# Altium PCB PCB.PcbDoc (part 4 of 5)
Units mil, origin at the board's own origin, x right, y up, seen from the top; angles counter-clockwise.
Board outline 6700 x 6500 mil, 2 copper layers (Top Layer, Bottom Layer); 203 components, 278 nets, 1296 pads, 461 vias.
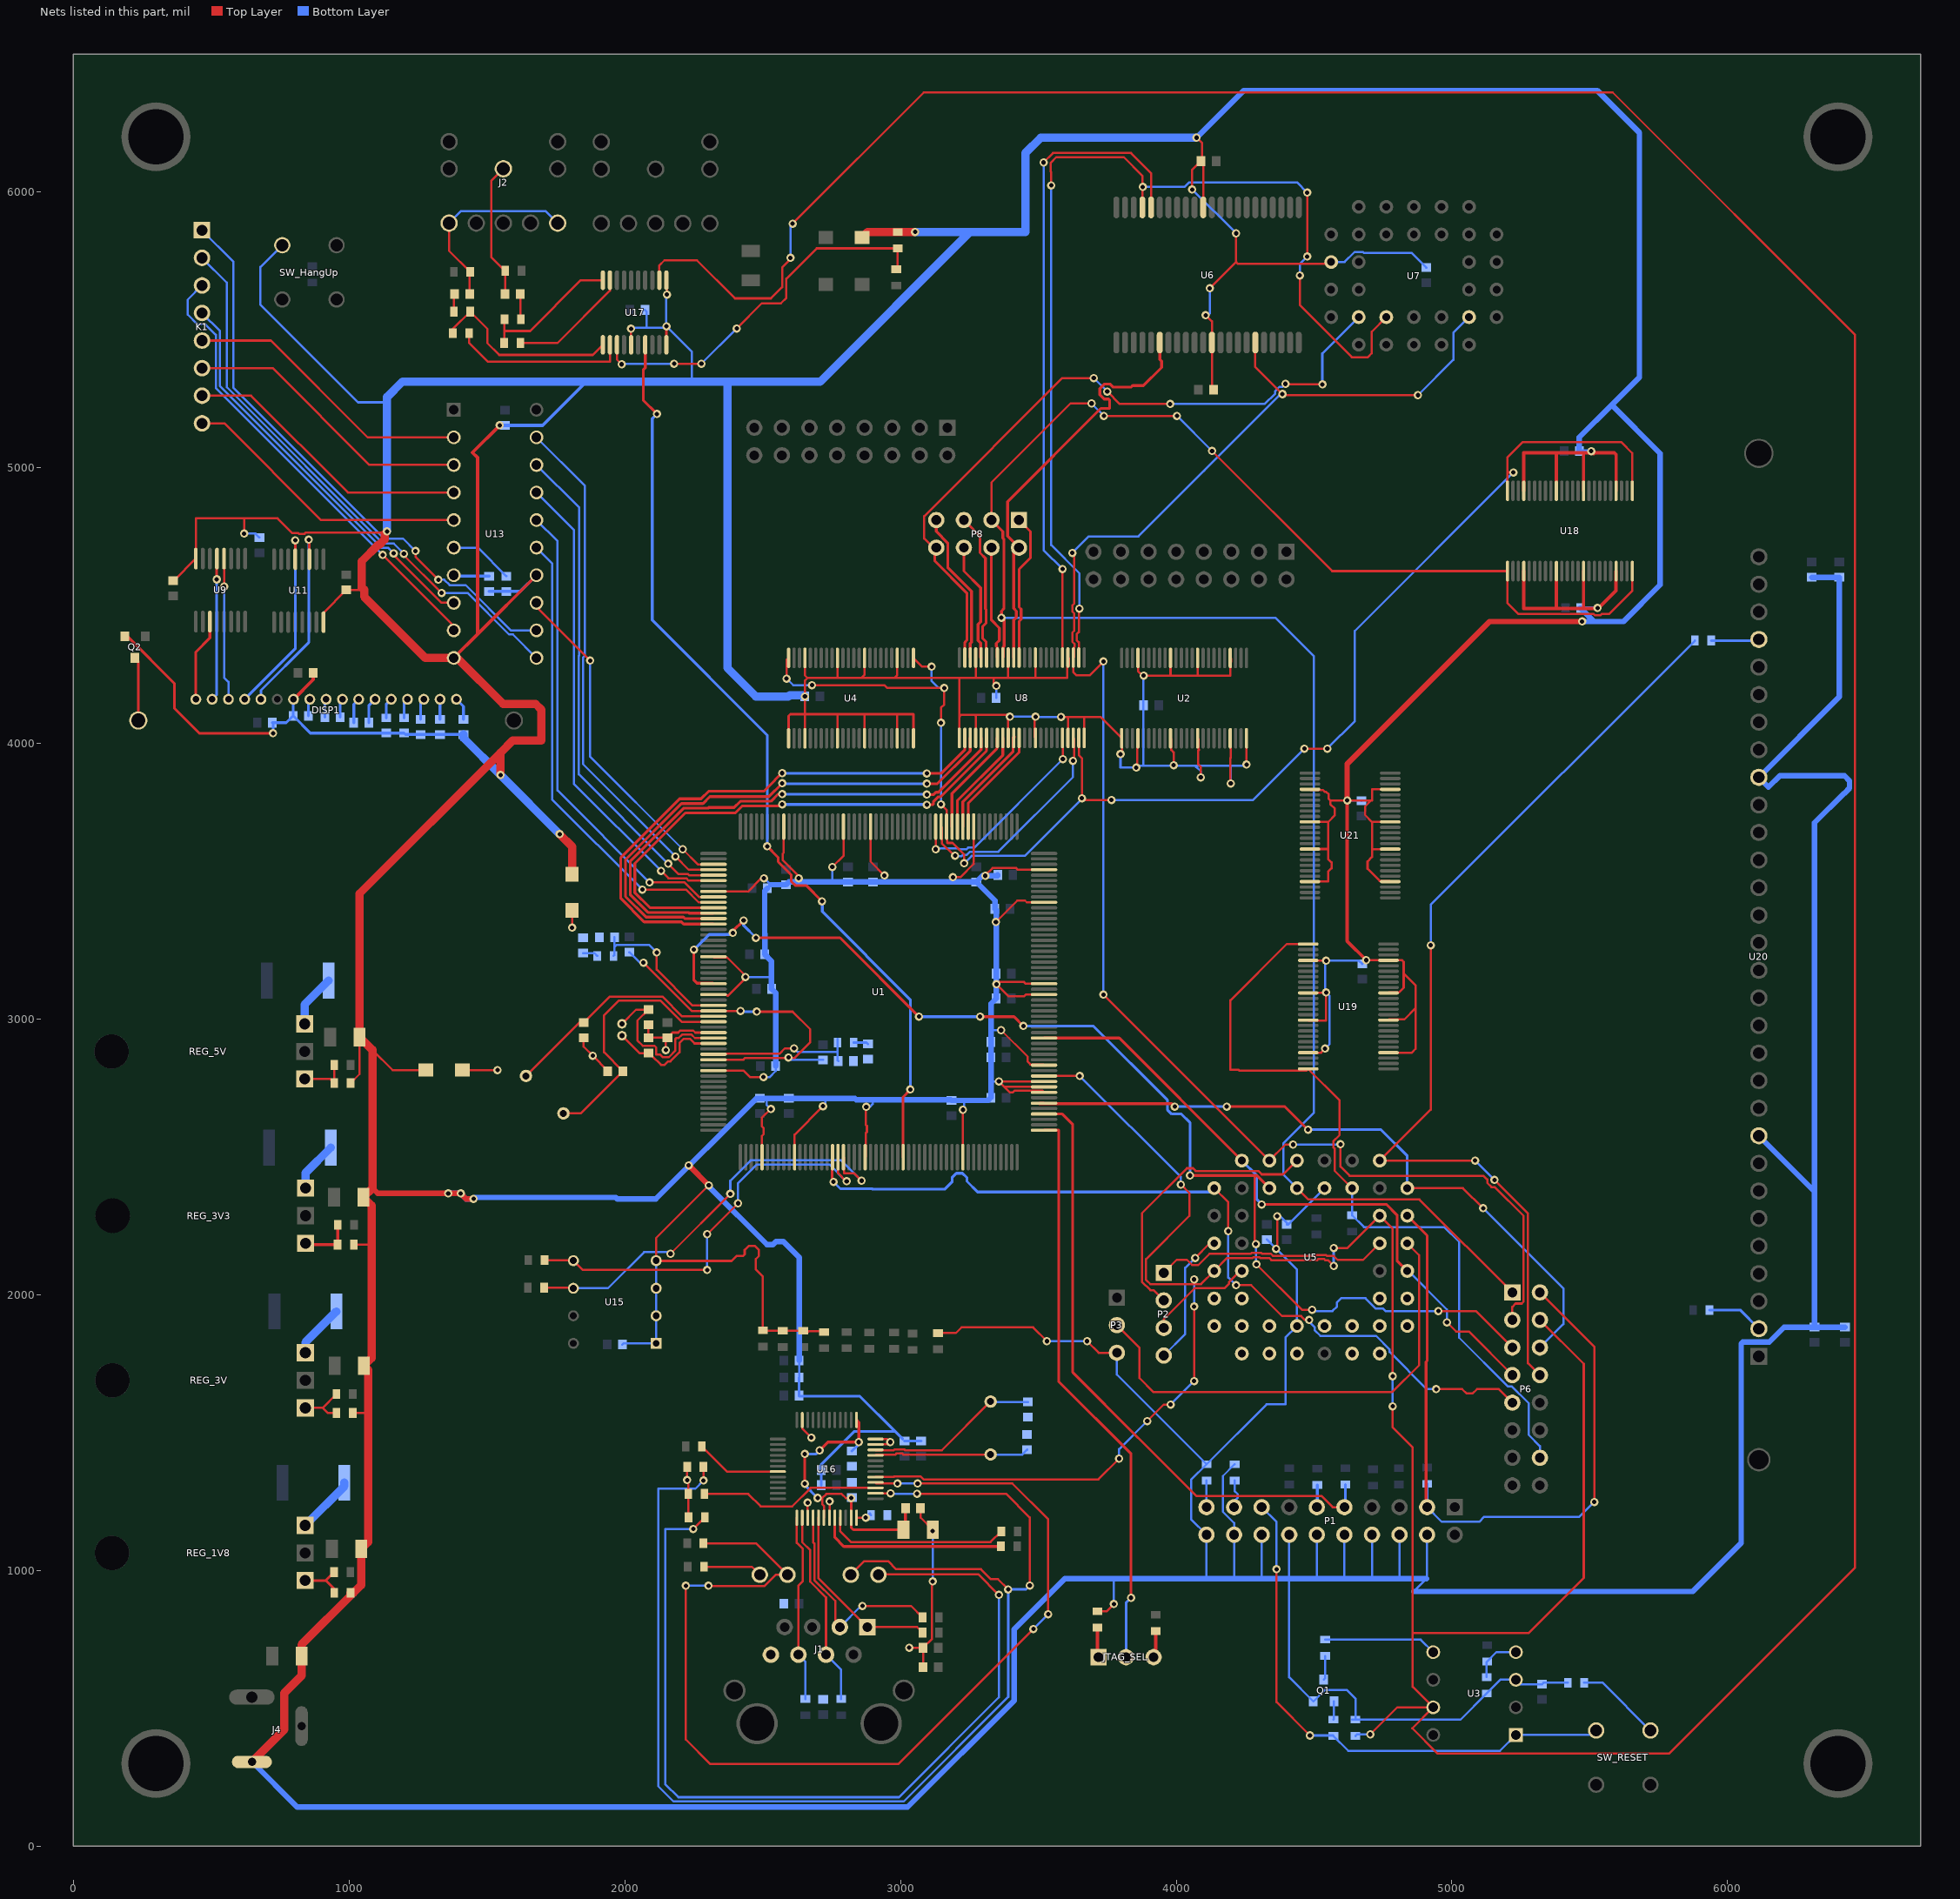
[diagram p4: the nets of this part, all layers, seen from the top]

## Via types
v1: diameter 30, hole 16, Top Layer to Bottom Layer, 461 vias

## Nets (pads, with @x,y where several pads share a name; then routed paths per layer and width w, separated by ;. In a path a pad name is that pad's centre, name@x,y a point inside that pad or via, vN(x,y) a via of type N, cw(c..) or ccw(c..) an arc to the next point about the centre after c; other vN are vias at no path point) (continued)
GND: C1.2 C2.2 C3.2 C4.2 C5.1 C6.2 C7.1 C8.2 C9.1 C10.2 C11.1 C12.2 C13.1 C14.2 C16.2 C18.2 C20.2 C21.2 C24.2 C25.2 C32.2 C33.2 C34.2 C36.2 C37.2 C38.2 C39.2 C41.2 C43.2 C44.1 C45.1 C46.1 C47.1 C48.1 C49.2 C50.2 C51.2 C52.2 C53.2 C54.2 C56.2 C57.2 C59.2 C60.2 C61.2 C63.2 C65.2 C66.2 C67.2 C68.2 C69.2 C70.2 C71.1 C72.1 C74.1 C75.2 C76.1 C77.2 C78.1 C79.1 C81.2 C82.2 C83.2 C84.2 C85.2 C86.2 C87.2 C88.2 C89.2 C90.2 C91.2 C92.2 C93.2 DISP1.11 J1.8 J4.GND L2.2 L3.2 L4.2 P1.4 P1.6 P1.8 P1.10 P1.12 P1.14 P1.16 P1.18 P1.20 P3.3 Q1.2 Q2.S R4.1 R6.2 R13.2 R14.2 R19.1 R20.1 R21.1 R35.2 R36.1 R37.1 R38.1 R39.2 R40.2 R48.1 R50.1 R52.1 R54.1 R64.1 R65.2 R66.2 SW_HangUp.2 U1.8 U1.20 U1.27 U1.41 U1.57 U1.63 U1.76 U1.94 U1.112 U1.113 U1.114 U1.117 U1.130 U1.132 U1.147 U1.153 U1.165 U1.184 U1.189 U1.200 U2.4 U2.10 U2.15 U2.21 U2.25 U2.28 U2.34 U2.39 U2.45 U2.48 U3.3 U4.4 U4.10 U4.15 U4.21 U4.25 U4.28 U4.34 U4.39 U4.45 U4.48 U5.1 U5.23 U6.12 U6.34 U7.16 U8.4 U8.10 U8.15 U8.21 U8.25 U8.28 U8.34 U8.39 U8.45 U8.48 U9.8 U11.8 U13.10 U13.14 U15.1 U15.2 U15.3 U15.4 U16.15 U16.19 U16.35 U16.36 U16.47 U17.1 U17.15 U17.20 U18.4 U18.10 U18.15 U18.21 U18.28 U18.34 U18.39 U18.45 U19.4 U19.10 U19.15 U19.21 U19.28 U19.34 U19.39 U19.45 U20.9 U20.22 U21.4 U21.10 U21.15 U21.21 U21.28 U21.34 U21.39 U21.45 | length 69308.9
  Top Layer w8: C10.2@362,4590.56 364.82,4590.56 U9.8@444.43,4670.17 444.43,4816 620,4816 ; v1(620,4761) 620,4816 ; U11.8@907.57,4439.83 907.57,4474.01 C16.2@990,4556.44 1053.44,4556.44 1046,4563.88 ; R50.1@1005.53,2768 1038.15,2800.62 C74.1@1038.15,2935 ; R54.1@1013.53,1572 1068,1572 1069,1573 ; R52.1@1017.53,2182 1078,2182 1082,2186 ; 1085,2888.15 1158.15,2815 L4.2@1279.06,2815 ; v1(1138,4769) 1129.43,4760.43 1124.87,4765 843.23,4765 838.66,4760.43 818.34,4760.43 815.97,4762.8 794.43,4762.8 741.23,4816 620,4816 ; U17.15@2023.18,5445.75 v1(2023.18,5504.18) ; U17.20@2151.13,5445.75 v1(2151.13,5512.87) ; U17.1@2151.13,5680 2153,5678.13 v1(2153,5628) ; R20.1@2226.47,1376 v1(2226.47,1328.53) 2230.47,1324.53 R19.1@2230.47,1278 2231.47,1277 R21.1@2231.47,1193 ; v1(2305,2397) 2114,2206 U15.4@2114,2124 2115,2123 2387.23,2123 2405.23,2141 2428.79,2141 2435,2147.21 2435,2162.77 2450.23,2178 2471.77,2178 2487,2162.77 2487,2141.23 2476,2130.23 2476,2091.77 2501,2066.77 R39.2@2501,1871.53 2503,1869.53 R38.1@2573,1869.53 R37.1@2647,1869.53 2651,1865.53 2665.29,1865.53 2667.76,1868 2720.53,1868 R36.1@2723,1865.53 ; U1.41@2321.77,2813.39 2430.84,2813.39 2454.23,2790 v1(2503,2790) ; U1.27@2321.77,3088.98 2368.32,3088.98 2373.21,3084.08 2438,3148.87 v1(2438,3153) 2438,3157.09 2371.1,3223.99 2324.55,3223.99 U1.20@2321.77,3226.77 ; U1.8@2321.77,3462.99 2447.29,3462.99 2495.3,3511 v1(2505,3511) ; U1.57@2497.95,2499.41 2497.95,2576.65 2504.27,2582.96 2504.27,2604.5 2497.95,2610.82 2497.95,2642.95 2529,2674 v1(2530,2674) ; U1.200@2576.69,3698.23 2576.69,3603.45 2572.63,3599.39 2572.63,3577.37 2631,3519 v1(2631,3511) ; U4.25@2594.41,4018.66 2594.41,4099.41 2601,4106 2653.47,4106 ; U1.63@2616.06,2499.41 2616.06,2581.06 v1(2719,2684) ; U16.47@2643.89,1546 2643.89,1515.11 v1(2677,1482) ; U4.28@2653.47,4018.66 2653.47,4106 ; U4.21@2653.47,4310 2653.47,4246.54 2663,4237 ; U16.15@2663.57,1191.67 v1(2663.57,1246.43) ; U16.19@2742.31,1191.67 2743,1192.35 v1(2743,1251) ; v1(2753,3552) 2793.23,3592.23 U1.189@2793.23,3698.23 ; U4.34@2771.58,4018.66 2771.58,4105.58 2772,4106 ; U4.15@2771.58,4310 2771.58,4238.58 2770,4237 ; U4.39@2870,4018.66 2870,4105 2871,4106 ; U4.10@2870,4310 2870,4249 2858,4237 ; U1.76@2871.97,2499.41 2874.75,2502.19 2874.75,2587.41 2878.28,2590.95 2878.28,2612.49 2874.75,2616.02 2874.75,2680.75 v1(2876,2682) ; U1.184@2891.65,3698.23 2891.65,3571.35 v1(2942,3521) ; U16.35@2909.64,1457.42 2954.42,1457.42 v1(2963,1466) 2951.9,1477.1 U16.36@2909.64,1477.1 ; U4.45@2988.11,4018.66 2988.11,4104.89 2987,4106 ; U4.4@2988.11,4310 2988.11,4248.11 2977,4237 ; v1(3032,720) C81.2@3082.44,720 ; U4.48@3047.17,4018.66 3047.17,4105.84 3047,4106 2987,4106 ; C63.2@3073.12,1226 3073.12,1192.03 C61.2@3117.15,1148 v1(3117.15,1142.85) ; C86.2@3082.44,650 C81.2@3082.44,720 ; v1(3117.15,960.85) 3114.75,958.45 3114.75,752.31 C81.2@3082.44,720 ; R35.2@3136,1861.53 3201,1861.53 3221.47,1882 3481,1882 v1(3531,1832) ; v1(3190,3515) 3217.77,3515 3265.67,3562.9 U1.165@3265.67,3698.23 ; U8.25@3213.78,4020 3213.78,4097 ; U1.94@3226.3,2499.41 v1(3226.3,2671.3) ; U8.28@3272.84,4020 3272.84,4100.06 3270,4102.89 ; U8.21@3272.84,4311.34 3272.84,4237.84 3272,4237 ; v1(3308,3520) 3308,3522 3334.05,3548.05 3419.72,3548.05 3426.04,3541.73 U1.153@3520.59,3541.73 ; v1(3346,3352) 3423.94,3429.94 3451.71,3429.94 3458.02,3423.62 U1.147@3520.59,3423.62 ; v1(3347.56,4208.56) 3338,4218.12 3338,4237 ; v1(3365,2960) 3461.36,2863.64 3461.36,2845.75 3471.27,2835.85 3517.81,2835.85 U1.117@3520.59,2833.07 ; U8.34@3390.95,4020 3390.95,4090.95 v1(3397,4097) 3391.11,4102.89 3270,4102.89 ; U8.15@3393.44,4313.83 U8.15@3390.95,4311.34 3390.95,4240.95 3387,4237 ; U8.39@3489.37,4020 3486.59,4022.78 3486.59,4093.59 v1(3490,4097) ; U8.10@3489.37,4311.34 3489.37,4237.37 3489,4237 ; U1.112@3520.59,2734.65 3514.27,2740.96 3414.19,2740.96 3407.88,2734.65 3396.39,2734.65 3376.7,2754.33 ; U1.113@3520.59,2754.33 3376.7,2754.33 ; U1.114@3520.59,2774.02 v1(3357.02,2774.02) 3376.7,2754.33 ; U1.130@3520.59,3088.98 3454.75,3088.98 3448.43,3082.66 3392.34,3082.66 v1(3348,3127) 3355.66,3134.66 3448.43,3134.66 3454.75,3128.35 U1.132@3520.59,3128.35 ; v1(3582,4096) 3607,4096 ; U8.45@3607.48,4020 3607.48,4095.52 3607,4096 ; U8.4@3607.48,4311.34 3610.26,4308.56 3610.26,4283 3605,4277.74 3605,4237 3489,4237 ; U8.48@3666.54,4020 3666.54,4095.47 3666,4096 ; v1(3677,1832) 3719,1790 P3.3@3785,1790 ; R6.2@3714,852 3747,852 v1(3774,879) ; v1(3798,3961) 3804.11,3967.11 3804.11,4016.76 U2.25@3802.21,4018.66 3724.87,4096 3666,4096 ; v1(3855,3912) 3858.48,3915.48 3858.48,4015.88 U2.28@3861.26,4018.66 ; U2.21@3861.26,4310 3861.26,4262.74 3880,4244 v1(3882,4246) 3978,4246 ; U2.34@3979.37,4018.66 3982.15,4015.88 3982.15,3976.31 3991,3967.46 v1(3991,3921) ; U2.15@3979.37,4310 3979.37,4247.37 3978,4246 ; v1(4058,6009) 4058,6080.56 C3.2@4089.44,6112 C3.2@4094.44,6107 ; v1(4074,6197) 4094.44,6176.56 C3.2@4094.44,6107 ; U2.39@4077.8,4018.66 4080.57,4015.88 4080.57,3980.16 4083.26,3977.48 4083.26,3977.11 4080,3973.85 4080,3924.15 4089,3915.15 v1(4089,3877) ; U2.10@4077.8,4310 4077.8,4246.21 4078,4246 ; U6.34@4098,5944.08 4098,6103.44 C3.2@4094.44,6107 ; v1(4107,5553) 4129.5,5530.5 U6.12@4129.5,5454 4129.5,5289.06 C24.2@4135.56,5283 ; v1(4122,5651) 4217,5746 ; U2.45@4195.91,4018.66 4198,4016.57 4198,3948.02 4197,3947.02 4197,3856 v1(4198,3855) ; U2.4@4195.91,4310 4198.68,4307.22 4198.68,4296 4196,4293.32 4196,4246 4078,4246 ; v1(4217,5850) 4217,5746 ; U2.48@4254.96,4018.66 4254.96,3923.96 4255.92,3923 v1(4255,3923) ; v1(4362.44,2167) 4366,2170.56 v1(4366,2285) ; U19.45@4478.66,2878.47 4525.47,2878.47 v1(4540,2893) ; U19.39@4478.66,2996.58 4480.24,2995 4544,2995 v1(4544,3097) 4542,3095 U19.34@4478.66,3095 ; U19.28@4478.66,3213.11 4479.77,3212 v1(4544,3212) ; U21.45@4485,3498.78 4550.78,3498.78 4550.78,3534.68 4563.17,3547.07 4563.17,3568.6 4550.78,3580.99 4550.78,3616 ; U21.39@4485,3616.89 4549.89,3616.89 4550.78,3616 ; U21.34@4485,3715.32 4551.32,3715.32 ; U21.28@4485,3833.43 4487.78,3830.65 4532.59,3830.65 4539.12,3824.11 4544.1,3824.11 4553,3815.21 4553,3799 4559,3793 ; U7.16@4562,5746 4556,5740 4223,5740 4217,5746 ; v1(4689,3214) U19.21@4769.11,3214 ; U19.4@4770,2878.47 4854.47,2878.47 4868,2892 4868,3039.77 ; U19.10@4770,2996.58 4772.78,2999.35 4827.58,2999.35 4868,3039.77 ; U19.15@4770,3095 4772.78,3097.78 4808.5,3097.78 4825,3114.28 4825,3166 ; U19.21@4770,3213.11 U19.21@4769.11,3214 ; U21.4@4776.34,3498.78 4773.56,3501.56 4737.84,3501.56 4694,3545.4 4694,3571.77 4710.43,3588.19 4710.43,3615.58 ; U21.10@4776.34,3616.89 4773.56,3619.67 4761,3619.67 4756.91,3615.58 4710.43,3615.58 ; U21.15@4776.34,3715.32 4710.54,3715.32 4710.43,3715.43 ; U21.21@4776.34,3833.43 4710.43,3833.43 4710.43,3793 4707.23,3793 ; 2653.47,4106 2772,4106 ; 2653.47,4106 v1(2653.47,4170.54) 2653,4171 2653,4227 2663,4237 ; 2663,4237 2770,4237 ; 2770,4237 2858,4237 ; 2772,4106 2871,4106 ; 2858,4237 2977,4237 ; 2871,4106 2987,4106 ; 2977,4237 3215,4237 ; 3213.78,4097 3213.78,4235.78 3215,4237 ; 3213.78,4097 3219.67,4102.89 3270,4102.89 ; 3215,4237 3272,4237 ; 3272,4237 3338,4237 ; 3338,4237 3387,4237 ; 3387,4237 3489,4237 ; 3607,4096 3666,4096 ; 3978,4246 4078,4246 ; 4550.78,3616 4550.78,3714.78 4551.32,3715.32 ; 4551.32,3715.32 4575.56,3739.56 4575.56,3763.21 4559,3779.77 4559,3793 ; 4559,3793 v1(4620,3793) 4707.23,3793 ; 4707.23,3793 4685,3770.77 4685,3740.85 4710.43,3715.43 ; 4710.43,3615.58 4710.43,3715.43 ; U19.21@4769.11,3214 4818,3214 4825,3207 4825,3166 ; 4825,3166 4868,3123 4868,3039.77
  Top Layer w10: Q2.S@186.6,4388.74 195.7,4388.74 367,4217.44 367,4127 457,4037 v1(725,4037)
  Top Layer w12: DISP1.11@798.94,4160 870.56,4231.62 C79.1@870.56,4256 ; U13.10@1380,4310 1466,4396 ; v1(1546.44,5153.44) 1448,5055 1466,5037 1466,4396 ; U13.14@1680,4610 1466,4396 ; v1(4620,3793) 4620,3283 v1(4689,3214) ; U18.28@5260.63,4625 5260.63,4489.37 5380,4489.37 ; U18.21@5260.63,4916.34 5260.63,5053.63 5378,5053.63 ; U18.34@5378.74,4625 5378.74,4490.63 5380,4489.37 ; U18.15@5378.74,4916.34 5378.74,5052.89 5378,5053.63 ; U18.39@5477.17,4625 5477.17,4489.54 5477,4489.37 ; U18.10@5477.17,4916.34 5477.17,5051.8 5479,5053.63 ; v1(5505,5060) v1@5511.37,5053.63 ; v1@5514,5051 v1@5511.37,5053.63 ; v1(5528.37,4491) v1@5530,4489.37 ; U18.45@5595.28,4625 5594.5,4624.22 5594.5,4585.67 5594.37,4585.55 5594.37,4553.74 v1@5530,4489.37 ; U18.4@5595.28,4916.34 5595.28,5047.73 5589.37,5053.63 v1@5511.37,5053.63 ; 5378,5053.63 5479,5053.63 ; 5380,4489.37 5477,4489.37 ; 5477,4489.37 v1@5530,4489.37 ; 5479,5053.63 v1@5511.37,5053.63
  Top Layer w20: 1085,2386.85 1103.85,2368 v1(1360,2368) ; v1@1358,2370 v1(1360,2368) ; v1@1404,2369 v1(1405,2368) ; v1(1452,2348) 1425,2348 v1(1405,2368) ; v1(2232,2470) v1(2305,2397) ; v1(4620,3793) 4620,3925 5137,4442 v1(5472,4442) ; v1(1360,2368) v1(1405,2368)
  Top Layer w30: J4.GND@648,306 765,423 765,555 828.15,618.15 C71.1@828.15,690 828.15,731.15 R48.1@1016,919 ; R48.1@1005.53,919 R48.1@1016,919 ; 1046,4563.88 1046,4660.33 1106.67,4721 1111,4721 1129.43,4739.43 v1@1129.43,4760.43 ; 1055,4558 1055,4532 1277,4310 U13.10@1380,4310 1392,4310 1559,4143 1677,4143 1697,4123 1697,4011 1594,4011 1549.5,3966.5 ; v1(1549.5,3885.5) 1549.5,3966.5 ; v1(1764,3671) 1809,3626 L3.2@1809,3525.94 ; L2.2@2860.94,5835 2880.47,5854.53 R64.1@2990,5854.53 3052.53,5854.53 v1(3053,5855) ; R48.1@1016,919 1044.15,947.15 C72.1@1044.15,1079 1069,1103.85 1069,1573 1069,1728.15 C78.1@1054.15,1743 1082,1770.85 1082,2186 1082,2324.15 C76.1@1052.15,2354 1085,2386.85 1085,2888.15 C74.1@1038.15,2935 1038.15,3455.15 1549.5,3966.5
  Bottom Layer w8: v1(620,4761) 660.56,4761 C54.2@675,4746.56 ; SW_HangUp.2@758.15,5806.85 679,5727.7 679,5591 1033,5237 1138,5237 ; C2.2@1991.56,1820 1995.56,1824 U15.1@2114,1824 U15.2@2114,1924 U15.3@2114,2024 U15.4@2114,2124 ; v1(2023.18,5504.18) 2026,5507 2079,5507 ; C1.2@2073.56,5572 2079,5566.56 2079,5507 ; v1(2153,5628) 2149,5624 2150,5623 v1@2150,5514 ; 2243,5312 2243,5421 v1(2151.13,5512.87) v1@2150,5514 ; v1(2438,3153) 2532.56,3153 ; v1(2503,2790) 2526,2790 2547.56,2811.56 C67.2@2547.56,2830 ; v1(2505,3511) 2506.44,3511 2530,3487.44 C68.2@2517.56,3475 ; 2514,2712.56 2514,2690 v1(2530,2674) ; v1(2631,3511) v1@2635,3507 ; C88.2@2632.56,1700 C91.2@2632.56,1762 ; v1(2653.47,4170.54) 2654,4170 2654,4170.44 C20.2@2653.47,4170.98 ; v1(2719,2684) 2727,2692 2727,2712.56 ; v1(2753,3552) 2753,3498.44 2754,3497.44 ; v1(2876,2682) 2889,2682 2899,2692 2899,2707.56 ; 2942,3497.44 v1(2942,3521) ; v1(3117.15,960.85) v1(3117.15,1142.85) ; v1(3190,3515) 3190,3511.44 3204,3497.44 ; v1(3226.3,2671.3) 3231,2676 3231,2705 ; 3328.44,2776 3330.43,2774.02 v1(3357.02,2774.02) ; 3328.44,2966 3334.44,2960 v1(3365,2960) ; C6.2@3347.56,4165 v1(3347.56,4208.56) ; v1(3397,4097) v1(3490,4097) 3491,4096 v1(3582,4096) ; v1(3531,1832) v1(3677,1832) ; v1(3774,879) 3774,970 3775,971 ; P3.3@3785,1790 3785,1710.53 R14.2@4110,1385.53 ; v1(3798,3961) 3798,3912 v1(3855,3912) 3862.56,3919.56 3881.44,3919.56 ; v1(3882,4246) 3881.44,4245.44 C38.2@3881.44,4138 3881.44,3919.56 ; v1@3991,3916 v1@3991,3919.56 ; v1(3991,3921) v1@3991,3919.56 ; v1(4058,6009) v1(4217,5850) ; v1(4089,3877) 4089,3898.44 4072.44,3915 4077,3919.56 ; v1(4107,5553) 4115,5553 4122,5560 v1(4122,5651) ; 4109,971 4110,972 P1.20@4110,1130 4054,1186 4054,1329.53 R14.2@4110,1385.53 ; v1(4198,3855) 4198,3918.37 4196.81,3919.56 ; 4210,971 P1.18@4210,1130 4210,1172.69 4169.47,1213.21 4169.47,1343 R13.2@4212,1385.53 ; v1(4255,3923) 4255,3921 4253.56,3919.56 4196.81,3919.56 ; 4310,971 P1.16@4310,1130 ; C57.2@4329,2200.44 v1(4362.44,2167) 4438,2091.44 U5.1@4438,1887 4396,1845 4396,1603 4327.47,1603 R14.2@4110,1385.53 ; v1(4366,2285) 4377.12,2285 C56.2@4406.56,2255.56 ; C56.2@4401,2255.56 C56.2@4406.56,2255.56 ; P1.14@4410,1130 4410,971 4410,613.23 Q1.2@4497.6,525.63 4538.97,567 4619,567 4650,536 R66.2@4650,459.53 ; 4507,971 4510,974 P1.12@4510,1130 ; U5.23@4538,2387 C56.2@4406.56,2255.56 ; v1(4540,2893) 4556,2909 4556,3085 v1(4544,3097) 4540.95,3100.06 4540.95,3208.95 v1(4544,3212) 4663,3212 C33.2@4675,3200 v1(4689,3214) ; U7.16@4562,5746 4611.09,5746 4647.09,5782 4676.91,5782 4679.91,5779 4854,5779 C12.2@4907,5726 ; 4607,971 4610,974 P1.10@4610,1130 ; v1(4620,3793) 4670.56,3793 C18.2@4672,3791.56 ; R66.2@4637.53,459.53 R66.2@4650,459.53 ; 4709,971 4710,972 P1.8@4710,1130 ; 4810,971 P1.6@4810,1130 ; 4861,924 4908,971 4910,973 P1.4@4910,1130 ; R65.2@5420.47,593 5332.44,593 C32.2@5327,587.56 5248.44,587.56 U3.3@5232,604 5175.53,604 R4.1@5126,554.47 5031.06,459.53 R66.2@4650,459.53 ; 2079,5507 2150,5507 v1@2150,5514 ; 3881.44,3919.56 v1@3991,3919.56 ; v1@3991,3919.56 4077,3919.56 ; 4077,3919.56 4195,3919.56 ; 4195,3919.56 4195.91,3920.46 4196.81,3919.56 ; 4195,3919.56 4196.81,3919.56
  Bottom Layer w10: v1(725,4037) 725,4072.56 C53.2@722.56,4075 772.44,4075 C39.2@797.44,4100 ; DISP1.11@798.94,4160 797.44,4158.5 C39.2@797.44,4100 ; C44.1@1415,4032.44 C45.1@1330,4032.44 C46.1@1260,4032.44 1205,4032.44 C47.1@1200,4037.44 C48.1@1135,4037.44 860,4037.44 C39.2@797.44,4100 ; C87.2@2632.56,1632.44 2852.56,1632.44 2980,1505 ; C87.2@2632.56,1635 C88.2@2632.56,1700 ; C90.2@2712.44,1310 C89.2@2712.44,1365 2712.44,1384.44 2833,1505 2980,1505 ; C93.2@3007.9,1477.1 2980,1505 ; C93.2@3015,1470 C92.2@3075,1470
  Bottom Layer w12: C41.2@1508,4551.44 C43.2@1571,4551.44 1621.44,4551.44 U13.14@1680,4610 ; v1(1546.44,5153.44) C21.2@1566,5153.44 1702.44,5153.44 1861,5312 ; C50.2@5461.56,5060 v1(5505,5060) ; C14.2@5466.56,4491 v1(5528.37,4491)
  Bottom Layer w20: J4.GND@648,306 812,142 3025.7,142 3412,528.3 3412,787 3596,971 3775,971 4109,971 4210,971 4310,971 4410,971 4507,971 4607,971 4709,971 4810,971 4908,971 ; v1(1360,2368) v1(1405,2368) 1425,2348 v1(1452,2348) 1457.33,2353.33 1967.44,2353.33 1972.76,2348 2113,2348 2477.56,2712.56 C51.2@2490,2712.56 2514,2712.56 C13.1@2595,2712.56 2727,2712.56 2835,2712.56 2840,2707.56 2899,2707.56 3182.44,2707.56 C25.2@3185,2705 3231,2705 3317.44,2705 C34.2@3327.44,2715 3328.44,2716 3328.44,2776 C11.1@3328.44,2861 C37.2@3328.44,2917 3328.44,2966 3328.44,3056 C4.2@3347.44,3075 C36.2@3347.44,3165 3347.44,3395 C8.2@3342.44,3400 3342.44,3430 C49.2@3275,3497.44 ; v1@2229,2470 v1(2232,2470) ; v1(2305,2397) 2305,2392.75 2515.75,2182 2537.75,2182 2548.75,2193 2575.25,2193 2632.56,2135.7 C91.2@2632.56,1762 ; C68.2@2517.56,3475 2507.56,3465 2507.56,3308.69 2508,3308.25 2508,3235.44 C5.1@2507.56,3235 2532.56,3210 2532.56,3153 C52.2@2532.56,3110 2547.56,3095 C67.2@2547.56,2830 ; C68.2@2530,3487.44 C69.2@2585,3487.44 2595,3497.44 2754,3497.44 C9.1@2810,3497.44 C70.2@2900,3497.44 2942,3497.44 3204,3497.44 C49.2@3275,3497.44 ; C7.1@3352.44,3523 3352.44,3519.81 3297.37,3519.81 C49.2@3275,3497.44 ; v1(4074,6197) 4245,6368 5527,6368 5680,6215 5680,5328 5579.5,5227.5 ; 4861,924 5873,924 6049,1100 6049,1823 6055,1829 6151.38,1829 6204.93,1882.56 C84.2@6315,1882.56 ; C50.2@5461.56,5060 5461.56,5109.56 5579.5,5227.5 ; C14.2@5466.56,4491 5515.56,4442 ; v1(5472,4442) 5515.56,4442 ; U20.9@6113,2577 6315,2375 ; C83.2@6305,4602.44 C75.2@6405,4602.44 6405,4169 U20.22@6113,3877 6148.15,3841.85 6189.3,3883 6423.25,3883 6442,3864.25 6442,3837.75 6423.25,3819 6421.7,3819 6315,3712.3 6315,2375 ; C77.2@6425,1882.56 C84.2@6315,1882.56 ; 5515.56,4442 5622,4442 5755,4575 5755,5052 5579.5,5227.5 ; C84.2@6315,1882.56 6315,2375
  Bottom Layer w30: v1(1138,4769) 1138,5237 1138,5256.33 1193.67,5312 1861,5312 2243,5312 2372,5312 ; C44.1@1415,4032.44 1415,4020 v1(1549.5,3885.5) v1(1764,3671) ; C20.2@2653.47,4170.98 v1(2653.47,4170.54) 2653.22,4170.78 2650,4174 2597.67,4174 2594.21,4170.54 2475.47,4170.54 2372,4274 2372,5312 ; v1(3053,5855) 3252,5855 ; v1(4074,6197) 3509,6197 3454,6142 3454,5855 3252,5855 ; 2372,5312 2709,5312 3252,5855
GNDOSC: C19.1 C23.2 C27.2 C28.2 C30.2 L4.1 U1.34 | length 630.9
  Top Layer w8: L4.1@1410.94,2815 v1(1539,2815) ; C27.2@1851,2932.44 1851,2900 v1(1884,2867) 1938.44,2812.56 C23.2@1938.44,2811 ; C30.2@2086,2979.44 C28.2@2086,2931.56 2086.88,2932.44 C19.1@2155,2932.44 ; v1(2149,2888) 2149,2926.44 C19.1@2155,2932.44 ; U1.34@2321.77,2951.18 2256.01,2951.18 2248.2,2959 2201.8,2959 2193.99,2951.18 2173.74,2951.18 C19.1@2155,2932.44
GNDPLL: C15.1 C17.1 C22.2 C26.2 C29.2 C31.2 L3.1 U1.30 U1.39 | length 1389.6
  Top Layer w8: v1(1809,3332) L3.1@1809,3394.06 ; v1(2068,3205) 2243.08,3029.92 U1.30@2321.77,3029.92 v1(2420.08,3029.92) ; U1.39@2321.77,2852.76 2430.85,2852.76 2437.16,2859.07 v1@2592.07,2859.07 ; v1(2479,3027) 2609,3027 2673,2963 2673,2916.23 2615.84,2859.07 v1@2592.07,2859.07 ; v1(2594,2861) v1@2592.07,2859.07
  Bottom Layer w8: C15.1@2017,3243 2055,3205 v1(2068,3205) ; v1(2420.08,3029.92) 2423,3027 v1(2479,3027) ; v1(2594,2861) 2602.56,2852.44 C17.1@2719,2852.44
JTAG_NRST: P1.15 R67.1 SW_RESET.2 U3.1 | length 1992.5
  Top Layer w8: v1(4364,1005) 4364,523 v1(4485,402)
  Bottom Layer w8: P1.15@4310,1230 4364,1176 v1(4364,1005) ; v1(4485,402) 4568.47,402 R67.1@4570,400.47 4624.47,346 5174,346 U3.1@5232,404 5507.15,404 SW_RESET.2@5523.15,420
JTAG_NTRST: P1.3 P6.2 R12.1 U5.15 | length 2674
  Top Layer w8: P6.2@5319,2009 5516,1812 v1(5516,1249)
  Top Layer w10: U5.15@4838,2287 4910,2215 4910,1761.18 4906,1757.18 4906,1234 P1.3@4910,1230
  Bottom Layer w8: P1.3@4910,1230 4963,1177 5099,1177 5117,1195 5462,1195 v1(5516,1249)
  Bottom Layer w10: P1.3@4910,1230 R12.1@4910,1314.47
KEYPAD_D0: U1.4 U13.19 | length 1891.8
  Top Layer w8: v1(2184,3590) 2232.26,3541.73 U1.4@2321.77,3541.73
  Bottom Layer w8: U13.19@1680,5110 1854.94,4935.06 1854.94,4317.45 1848.63,4311.14 1848.63,3925.37 v1(2184,3590)
KEYPAD_D1: U1.5 U13.18 | length 1826.7
  Top Layer w8: v1(2157.84,3563.84) 2195.76,3525.91 2229.36,3525.91 2233.23,3522.05 U1.5@2321.77,3522.05
  Bottom Layer w8: U13.18@1680,5010 1835.26,4854.74 1835.26,4318.98 1833.63,4317.35 1833.63,3888.04 v1(2157.84,3563.84)
KEYPAD_D2: U1.6 U13.17 | length 1764.1
  Top Layer w8: v1(2131.67,3537.67) 2158.43,3510.91 2223.15,3510.91 2231.7,3502.36 U1.6@2321.77,3502.36
  Bottom Layer w8: U13.17@1680,4910 1815.57,4774.43 1815.57,3853.77 v1(2131.67,3537.67)
KEYPAD_D3: U1.9 U13.16 | length 1737.5
  Top Layer w8: v1(2089.91,3495.91) 2216.94,3495.91 2269.54,3443.31 U1.9@2321.77,3443.31
  Bottom Layer w8: U13.16@1680,4810 1756.52,4733.48 1756.52,3829.31 v1(2089.91,3495.91)
KEYPAD_D4: U1.10 U13.15 | length 1676.3
  Top Layer w8: v1(2063.75,3469.75) 2221.89,3469.75 2268.02,3423.62 U1.10@2321.77,3423.62
  Bottom Layer w8: U13.15@1680,4710 1736.83,4653.17 1736.83,3796.67 v1(2063.75,3469.75)
KEYPAD_RDY: U1.3 U13.13 | length 1247.7
  Top Layer w8: U13.13@1680,4510 1680,4495 v1(1874.63,4300.37) ; v1(2210.16,3616.16) 2264.9,3561.42 U1.3@2321.77,3561.42
  Bottom Layer w8: v1(1874.63,4300.37) 1874.63,3951.69 v1(2210.16,3616.16)
MICIN+: C62.1 J2.A J2.D R24.1 | length 719.6
  Top Layer w8: J2.D@1363.15,5887.15 1363.15,5786.38 R24.1@1439.53,5710 1437.56,5708.03 C62.1@1437.56,5630
  Bottom Layer w8: J2.D@1363.15,5887.15 1407,5931 1713,5931 J2.A@1756.85,5887.15
MICIN-: C64.1 J2.E R33.2 | length 493.1
  Top Layer w8: J2.E@1560,6084 1516,6040 1516,5764.47 R33.2@1566.47,5714 C64.1@1566.47,5630.03
NBS1_3V3_BUF: U6.40 U8.5 | length 2382.4
  Top Layer w8: v1(3519,6107) 3553,6141 3836,6141 3909.02,6067.98 U6.40@3909.02,5944.08 ; U8.5@3587.8,4311.34 v1(3587.8,4632.2)
  Bottom Layer w8: v1(3519,6107) 3519,4701 v1(3587.8,4632.2)
NCS0: U1.166 U8.36 | length 398.1
  Top Layer w10: U1.166@3245.98,3698.23 3245.98,3783.86 3430.32,3968.19 U8.36@3430.32,4020
NCS1: U1.167 U8.35 | length 409.6
  Top Layer w10: U1.167@3226.3,3698.23 3226.3,3788.22 3408.85,3970.77 3408.85,4021.44 3409.02,4021.61 3412.41,4025 3412.41,4021.78 U8.35@3410.63,4020
NCS2: U1.168 U8.33 | length 390
  Top Layer w10: U1.168@3206.61,3698.23 3206.61,3792.57 3371.26,3957.22 U8.33@3371.26,4020
NCS3: U1.169 U8.32 | length 390
  Top Layer w10: U1.169@3186.93,3698.23 3186.93,3818.22 3349.8,3981.09 3349.8,4018.22 U8.32@3351.58,4020
NCS3V3B0: P8.1 U8.13 | length 538.8
  Top Layer w10: P8.1@3430,4810 3471.53,4768.47 3471.53,4673 3430.32,4631.79 3430.32,4493.91 3437.44,4486.79 3437.44,4450.33 3430.32,4443.21 U8.13@3430.32,4311.34
NCS3V3B1: P8.2 U6.6 U8.14 | length 1563.2
  Top Layer w10: U8.14@3410.63,4311.34 3410.63,4447.57 3420.44,4457.38 3420.44,4479.74 3410.63,4489.55 3410.63,4690.63 P8.2@3430,4710 3388.47,4751.53 3388.47,4876.66 3726.82,5215 3758.97,5215 3758.97,5244.4 3754.37,5249 3738.82,5249 3723,5264.82 3723,5287.18 3738.82,5303 3761.18,5303 3772.18,5292 3835.97,5292 3841.97,5298 3881.18,5298 3945.02,5361.83 3947,5363.82 3947,5386.18 3940.52,5392.66 U6.6@3940.52,5454
NCS3V3B2: P6.1 P8.3 U5.25 U8.16 U18.25 U18.48 | length 7724.6
  Top Layer w8: P8.3@3330,4810 3330,4946 3617,5233 v1(3693,5233) ; v1(3738,5188) v1(4003,5188) ; v1(4130,5061) 4566,4625 U18.25@5201.58,4625 5201.58,4508.42 5240,4470 5512.6,4470 5517.6,4465 5539.14,4465 5544.14,4470 5571,4470 5654.33,4553.33 U18.48@5654.33,4625 ; U5.25@4438,2387 4479,2346 4882,2346 P6.1@5219,2009
  Top Layer w10: P8.3@3330,4810 3371.47,4768.53 3371.47,4744.49 3375,4740.96 3375,4488.3 3366.44,4479.74 3366.44,4457.38 3375.89,4447.93 3375.89,4353.1 3373.04,4350.25 3373.04,4313.12 U8.16@3371.26,4311.34
  Bottom Layer w8: v1(3366,4456) 4360,4456 4499,4317 4499,2660 4389,2550 4389,2436 U5.25@4438,2387 ; v1(3693,5233) v1(3738,5188) ; v1(4003,5188) v1(4130,5061)
NCS3V3B3: P8.4 U8.17 | length 416.7
  Top Layer w10: P8.4@3330,4710 3330,4447.07 3358.89,4418.18 3358.89,4373.93 3347.89,4362.93 3347.89,4352.16 3349.8,4350.25 3349.8,4313.12 U8.17@3351.58,4311.34
NCS3V3B4: P8.5 U8.19 | length 542.6
  Top Layer w10: P8.5@3230,4810 3288.47,4751.53 3288.47,4691.27 3308,4671.74 3308,4487.96 3310.43,4485.53 3310.43,4436.61 3298.44,4424.63 3298.44,4380.37 3310.43,4368.39 3310.43,4313.12 U8.19@3312.21,4311.34
NCS3V3B5: P8.6 U8.20 | length 433.3
  Top Layer w10: P8.6@3230,4710 3230,4625 3290.74,4564.26 3290.74,4440.97 3281.44,4431.67 3281.44,4373.33 3290.74,4364.03 3290.74,4311.34 U8.20@3292.52,4311.34
NCS3V3B6: P8.7 U8.22 | length 553.5
  Top Layer w10: P8.7@3130,4810 3130,4768.73 3171.53,4727.2 3171.53,4638.47 3257.78,4552.22 3257.78,4366.99 3253.15,4362.36 U8.22@3253.15,4311.34
NCS3V3B7: P8.8 U7.22 U8.23 | length 2615.3
  Top Layer w8: P8.8@3130,4710 3124.53,4704.53 3086,4743.06 3086,4824 3587,5325 v1(3701,5325) ; v1(3750,5276) 3795,5231 v1(3978,5231) ; v1(4396,5304) 4396,5303 4395,5302 v1(4530,5302)
  Top Layer w10: P8.8@3124.53,4704.53 3124.53,4661.43 3240.78,4545.18 3240.78,4374.04 3233.47,4366.72 U8.23@3233.47,4311.34
  Bottom Layer w8: v1(3701,5325) v1(3750,5276) ; v1(3978,5231) 4320.79,5231 4359,5269.21 4359,5277.77 4374.23,5293 4385,5293 v1(4396,5304) ; v1(4530,5302) 4530,5414 U7.22@4662,5546
NCS4: U1.11 U8.30 | length 1911.6
  Top Layer w10: U1.11@2321.77,3403.94 2091.38,3403.94 2036.75,3458.57 2036.75,3564.75 2220,3748 2401.34,3748 2426.4,3773.06 2565.24,3773.06 v1(2571,3778.82) ; v1(3096,3777.63) 3116.59,3777.63 3120,3781.04 3120,3790.18 3135.82,3806 3144.96,3806 3312.21,3973.24 U8.30@3312.21,4020
  Bottom Layer w10: v1(2571,3778.82) 3094.82,3778.82 v1(3096,3777.63)
NCS5: U1.12 U8.29 | length 1934.4
  Top Layer w10: U1.12@2321.77,3384.25 2233.71,3384.25 2231.02,3386.94 2084.34,3386.94 2019.75,3451.53 2019.75,3571.79 2212.96,3765 2301.96,3765 2304.64,3767.69 2396.99,3767.69 2419.36,3790.06 2529.91,3790.06 2555.67,3815.82 v1(2571,3815.82) ; v1(3096,3814.63) 3120.4,3814.63 3128.77,3823 3137.92,3823 3292.52,3977.6 U8.29@3292.52,4020
  Bottom Layer w10: v1(2571,3815.82) 3094.82,3815.82 v1(3096,3814.63)
NCS6: U1.13 U8.27 | length 1948
  Top Layer w10: U1.13@2321.77,3364.57 2218.38,3364.57 2213.01,3369.94 2077.3,3369.94 2002.75,3444.48 2002.75,3578.83 2205.92,3782 2283.94,3782 2309,3807.06 2522.87,3807.06 v1(2571,3855.19) ; v1(3096,3854) 3133.91,3854 3253.15,3973.24 U8.27@3253.15,4020
  Bottom Layer w10: v1(2571,3855.19) 2572.19,3854 v1(3096,3854)
NCS7: U1.14 U8.26 | length 1976.8
  Top Layer w10: U1.14@2321.77,3344.88 2214.02,3344.88 2205.96,3352.94 2070.26,3352.94 1985.75,3437.44 1985.75,3585.88 2198.88,3799 2276.9,3799 2304.64,3826.74 2505.56,3826.74 2544,3865.19 2544,3866.37 2569.82,3892.19 v1(2571,3892.19) ; v1(3096,3891) 3146.87,3891 3233.47,3977.6 U8.26@3233.47,4020
  Bottom Layer w10: v1(2571,3892.19) 2572.19,3891 v1(3096,3891)
NetC22_1: C22.1 R1.2 U1.29 | length 558.8
  Top Layer w8: v1(2116,3242) 2116,3180 2246.39,3049.61 U1.29@2321.77,3049.61
  Bottom Layer w8: R1.2@1959.53,3229 1963.23,3232.71 1963.23,3262 ; C22.1@1963.23,3297 1963.23,3262 ; v1(2116,3242) 2088.25,3269.75 1970.98,3269.75 1963.23,3262
NetC23_1: C23.1 U1.32 X1.2 | length 960.9
  Top Layer w8: X1.2@1777.76,2658.24 1840.79,2658.24 C23.1@1993.56,2811 1925,2879.56 1925,3014 1978,3067 2130,3067 2206.45,2990.55 U1.32@2321.77,2990.55
NetC26_1: C26.1 R1.1 | length 55.8
  Bottom Layer w8: C26.1@1849,3239.44 1890.03,3239.44 R1.1@1900.47,3229
NetC27_1: C27.1 U1.31 X1.1 | length 829
  Top Layer w8: X1.1@1642,2794 1835.56,2987.56 C27.1@1851,2987.56 1945.44,3082 2136.21,3082 2208.21,3010 2321.54,3010 U1.31@2321.77,3010.24
NetC28_1: C28.1 U1.36 X2.2 | length 448
  Top Layer w8: X2.2@1990,2940 2053.56,2876.44 C28.1@2086,2876.44 2099.72,2876.44 2099.72,2866.07 2131.79,2834 2144.21,2834 2157.21,2847 2165.98,2847 2198.72,2879.73 2198.72,2913.49 2214.23,2929 2235.77,2929 2252.96,2911.81 U1.36@2321.77,2911.81
NetC29_1: C29.1 R2.2 U1.38 | length 545.8
  Top Layer w8: U1.38@2321.77,2872.44 2323.4,2874.07 2561.07,2874.07 2581,2894 v1(2614,2894)
  Bottom Layer w8: v1(2614,2894) 2627.19,2880.81 2769.28,2880.81 2771.47,2883 ; R2.2@2771.47,2927.53 R2.2@2771.47,2915 2771.47,2883 ; C29.1@2774.44,2848 2771.47,2850.97 2771.47,2883
NetC30_1: C30.1 U1.35 X2.1 | length 624.8
  Top Layer w8: X2.1@1990,2983 2041.56,3034.56 C30.1@2086,3034.56 2046,2994.56 2046,2922.54 2065.35,2903.19 2108.27,2903.19 2114.72,2896.75 2114.72,2872.28 2127.95,2872.28 2138.23,2862 2159.77,2862 2183.72,2885.95 2183.72,2927.82 2187.39,2931.5 2195.51,2931.5 2208.02,2944 2241.98,2944 2254.49,2931.5 U1.35@2321.77,2931.5
NetC31_1: C31.1 R2.1 | length 53.7
  Bottom Layer w8: R2.1@2830.53,2915 2876.56,2915 C31.1@2882,2909.56
NetC39_1: C39.1 DISP1.10 | length 62.3
  Bottom Layer w10: C39.1@852.56,4100 852.56,4154.56 DISP1.10@858,4160
NetC40_1: C40.1 DISP1.8 | length 68.5
  Bottom Layer w10: C40.1@967.56,4095 967.56,4151.45 DISP1.8@976.11,4160
NetC40_2: C40.2 DISP1.9 | length 66.9
  Bottom Layer w10: C40.2@912.44,4095 912.44,4155.38 DISP1.9@917.06,4160
NetC41_1: C41.1 U13.7 | length 129.4
  Bottom Layer w12: U13.7@1380,4610 1383.44,4606.56 C41.1@1508,4606.56
NetC42_1: C42.1 DISP1.6 | length 94
  Bottom Layer w10: C42.1@1072.56,4075 1072.56,4138.34 DISP1.6@1094.22,4160
NetC42_2: C42.2 DISP1.7 | length 92.3
  Bottom Layer w10: C42.2@1017.44,4075 1017.44,4142.27 DISP1.7@1035.17,4160
NetC43_1: C43.1 U13.6 | length 233.8
  Bottom Layer w8: U13.6@1380,4710 1467.56,4710 C43.1@1571,4606.56
NetC44_2: C44.2 DISP1.1 | length 83
  Bottom Layer w10: DISP1.1@1389.5,4160 1415,4134.5 C44.2@1415,4087.56
NetC45_2: C45.2 DISP1.2 | length 72.6
  Bottom Layer w10: C45.2@1330,4087.56 1330,4159.56 DISP1.2@1330.44,4160
NetC46_2: C46.2 DISP1.3 | length 77.2
  Bottom Layer w10: C46.2@1260,4087.56 1260,4148.61 DISP1.3@1271.39,4160
NetC47_2: C47.2 DISP1.4 | length 72.5
  Bottom Layer w10: C47.2@1200,4092.56 1200,4147.67 DISP1.4@1212.33,4160
NetC48_2: C48.2 DISP1.5 | length 75
  Bottom Layer w10: C48.2@1135,4092.56 1135,4141.72 DISP1.5@1153.28,4160
NetC59_1: C59.1 U16.34 X3.2 | length 629.8
  Top Layer w8: U16.34@2909.64,1437.73 2911.37,1436 2976.02,1436 2979.38,1439.36 3013.34,1439.36 3016.71,1436 3150,1436 X3.2@3327,1613
  Bottom Layer w8: X3.2@3327,1613 3328.44,1611.56 C59.1@3462,1611.56
NetC60_1: C60.1 U16.33 X3.1 | length 560.6
  Top Layer w8: U16.33@2909.64,1418.05 2912.59,1421 2982.23,1421 2985.59,1424.36 3007.13,1424.36 3010.49,1421 X3.1@3327,1421
  Bottom Layer w8: X3.1@3327,1421 3441.56,1421 C60.1@3459,1438.44
NetC61_1: C61.1 C63.1 C65.1 C66.1 U16.18 U16.23 U16.37 | length 1108
  Top Layer w8: U16.18@2722.63,1191.67 2722.63,1234.23 2716.31,1240.54 2716.31,1263.31 2731,1278 2786.77,1278 2801.77,1263 v1(2821,1263)
  Top Layer w10: v1(2653,1315) v1(2653,1423) ; v1(2699.69,1263.31) 2716.31,1263.31 ; v1(2707,1436) 2737,1466 v1(2849,1466) 2849,1537.74 U16.37@2840.74,1546 ; v1(2821,1263) 2821.05,1262.95 U16.23@2821.05,1191.67 2821.05,1155.95 2829,1148 C61.1@3010.85,1148 3018,1155.15 C63.1@3018,1226
  Bottom Layer w10: v1(2653,1315) 2653,1310 v1(2699.69,1263.31) ; v1(2653,1423) 2694,1423 v1(2707,1436) ; C65.1@2824,1433.56 2849,1458.56 v1(2849,1466)
NetC62_2: C62.2 R26.1 | length 64.8
  Top Layer w8: R26.1@1380.47,5566 1380.47,5628.03 C62.2@1382.44,5630
NetC64_2: C64.2 R32.1 | length 92.6
  Top Layer w8: C64.2@1621.56,5630 1621.56,5539.5 R32.1@1623.06,5538
NetDISP1_13: DISP1.13 U11.11 | length 722.5
  Top Layer w10: v1(854,4739) 856.39,4736.61 U11.11@856.39,4668.17
  Bottom Layer w10: DISP1.13@680.83,4160 680.83,4192.83 854,4366 v1(854,4739)
NetDISP1_14: DISP1.14 U11.13 | length 721.4
  Top Layer w10: U11.13@805.2,4668.17 v1(805.2,4736.8)
  Bottom Layer w10: DISP1.14@621.78,4160 805.2,4343.42 v1(805.2,4736.8)
NetDISP1_15: DISP1.15 U9.4 | length 516.8
  Top Layer w8: U9.4@546.8,4670.17 547,4669.97 v1(547,4569)
  Bottom Layer w8: v1(547,4569) 547,4239 562.72,4223.28 DISP1.15@562.72,4160
NetDISP1_16: DISP1.16 U9.5 | length 517.4
  Top Layer w8: v1(520,4595) 520,4668.97 U9.5@521.2,4670.17
  Bottom Layer w8: DISP1.16@503.67,4160 520,4176.33 v1(520,4595)
NetDISP1_17: DISP1.17 U9.11 | length 303
  Top Layer w10: DISP1.17@444.61,4160 444.61,4331.61 495.61,4382.61 U9.11@495.61,4441.83
NetDISP1_19: DISP1.19 Q2.D | length 231.7
  Top Layer w10: Q2.D@224,4310 235.95,4298.05 DISP1.19@235.95,4083.23
NetJ1_1: J1.1 R41.1 U16.17 | length 678.8
  Top Layer w8: U16.17@2702.94,1191.67 2702.94,972.06 J1.1@2880,795 3060.47,795 R41.1@3080.47,775
NetJ1_3: J1.3 R42.1 U16.16 | length 786.5
  Top Layer w8: U16.16@2683.26,1191.67 2683.26,1102.74 2687.94,1098.06 2687.94,965.84 2764,889.79 2764,811 J1.3@2780,795 ; v1(2862,872) 3038.47,872 R42.1@3080.47,830
  Bottom Layer w8: J1.3@2780,795 2857,872 v1(2862,872)
NetJ1_4: J1.4 R43.1 U16.14 | length 715.6
  Top Layer w8: U16.14@2643.89,1191.67 2643.89,1103.11 2672.94,1074.06 2672.94,959.63 2730,902.57 J1.4@2730,695
  Bottom Layer w8: J1.4@2730,695 2785,640 R43.1@2785,534.53
NetJ1_6: J1.6 R44.1 U16.13 | length 682.3
  Top Layer w8: U16.13@2624.2,1191.67 2624.2,1100.8 2645,1080 2645,961 2630,946 J1.6@2630,695
  Bottom Layer w8: J1.6@2630,695 2655,670 R44.1@2655,534.53
NetJ1_9: J1.9 R21.2 | length 3306.5
  Top Layer w8: v1(2248.53,1151) R21.2@2290.53,1193 ; J1.9@2920,985 2921.85,986.85 3282.15,986.85 v1(3357,912)
  Bottom Layer w8: v1(2248.53,1151) 2147,1151 2147,226 2195,178 2995,178 3357,540 v1(3357,912)
NetJ1_10: J1.10 R20.2 U16.26 | length 4702.8
  Top Layer w8: v1(2285.53,1326.53) R20.2@2285.53,1376 ; J1.10@2820,985 2869,1034 2955,1034 2984,1005 3292,1005 3328,969 3354,969 v1(3391,932) ; U16.26@2909.64,1280.25 v1(2964.25,1280.25) ; v1(3060,1279) 3383,1279 3469,1193 v1(3469,946)
  Bottom Layer w8: v1(2285.53,1326.53) 2256,1297 2122,1297 2122,218 2177,163 3012,163 3391,542 v1(3391,932) 3455,932 v1(3469,946) ; v1(2964.25,1280.25) 2965.5,1279 v1(3060,1279)
NetJ1_11: J1.11 R18.2 U16.28 | length 3897.6
  Top Layer w8: v1(2222,945) 2222,387 2311,298 2992,298 v1(3482,788) ; R18.2@2285.53,1099 2476,1099 J1.11@2590,985 2547.98,985 2506.98,944 2304,944 v1(2304,945) ; U16.28@2909.64,1319.62 2913.26,1316 v1(2989,1316) ; v1(3062,1316) 3406,1316 3536,1186 v1(3536,842)
  Bottom Layer w8: v1(2222,945) v1(2304,945) ; v1(2989,1316) v1(3062,1316) ; v1(3482,788) v1(3536,842)
NetJ1_12: J1.12 R22.2 | length 214.5
  Top Layer w8: R22.2@2287.53,1014 2461,1014 J1.12@2490,985
NetJTAG_SEL_1: JTAG_SEL.1 R6.1 | length 108.6
  Top Layer w12: R6.1@3714,792.94 3714,690 JTAG_SEL.1@3718,686
NetJTAG_SEL_2: JTAG_SEL.2 U1.105 | length 2080.3
  Top Layer w10: U1.105@3520.59,2596.85 3573.82,2596.85 3573.82,1686.18 3836.16,1423.84 v1(3836.16,901.16)
  Bottom Layer w10: JTAG_SEL.2@3818,686 3818,883 v1(3836.16,901.16)
NetJTAG_SEL_3: JTAG_SEL.3 R5.1 | length 98.3
  Top Layer w12: JTAG_SEL.3@3918,686 3926,694 R5.1@3926,780.94
NetK1_1: K1.1 U13.12 | length 2094.5
  Top Layer w8: v1(1241,4698) 1241,4677 v1(1324,4594)
  Bottom Layer w8: K1.1@467,5861 580,5748 580,5290.23 1127.23,4743 1196,4743 v1(1241,4698) ; v1(1324,4594) 1345.09,4594 1365.09,4574 1423,4574 1587,4410 U13.12@1680,4410
NetK1_2: K1.2 U13.11 | length 2039.9
  Top Layer w8: v1(1199,4688) 1199,4682.23 1335.23,4546 v1(1336,4546)
  Bottom Layer w8: K1.2@467,5761 557,5671 557,5292.02 1124.02,4725 1162.77,4725 1188,4699.77 1188,4699 v1(1199,4688) ; v1(1336,4546) 1429.79,4546 1580.79,4395 1595,4395 U13.11@1680,4310
NetK1_3: K1.3 U13.9 | length 1689.2
  Top Layer w8: v1(1122,4684) 1380,4426 U13.9@1380,4410
  Bottom Layer w8: K1.3@467,5661 415,5609 415,5555.02 450.02,5520 479,5520 517,5482 517,5289 v1(1122,4684)
NetK1_4: K1.4 U13.8 | length 1469
  Top Layer w8: v1(1162,4689) 1162,4683.23 1335.23,4510 U13.8@1380,4510
  Bottom Layer w8: K1.4@467,5561 532,5496 532,5295.8 1117.8,4710 1141,4710 v1(1162,4689)
NetK1_5: K1.5 U13.2 | length 1058.4
  Top Layer w8: K1.5@467,5461 717,5461 1068,5110 U13.2@1380,5110
NetK1_6: K1.6 U13.3 | length 1058.4
  Top Layer w8: K1.6@467,5361 723,5361 1074,5010 U13.3@1380,5010
NetK1_7: K1.7 U13.4 | length 1058.4
  Top Layer w8: K1.7@467,5261 645,5261 996,4910 U13.4@1380,4910
NetK1_8: K1.8 U13.5 | length 1058.4
  Top Layer w8: K1.8@467,5161 548,5161 899,4810 U13.5@1380,4810
NetP1_11: P1.11 R8.1 | length 81.3
  Bottom Layer w10: P1.11@4510,1230 4512,1232 R8.1@4512,1310.47
NetP1_17: P1.17 R13.1 | length 108.4
  Bottom Layer w8: P1.17@4210,1230 4212,1232 4212,1255.53 4214.69,1255.53 4223.47,1264.31 4223.47,1276.74 4212,1288.21 R13.1@4212,1326.47
NetP1_19: P1.19 R14.1 | length 96.5
  Bottom Layer w8: P1.19@4110,1230 R14.1@4110,1326.47
NetP2_1: P2.1 U5.14 | length 867.1
  Top Layer w8: P2.1@3955,2080 4002,2127 4039.23,2127 4058.23,2108 4079.77,2108 4120.77,2149 4271.02,2149 4274.02,2152 4307.98,2152 4310.98,2149 4343.67,2149 4351.67,2141 4505.02,2141 4509.02,2145 4542.98,2145 4546.98,2141 4571.77,2141 4585.77,2127 4678,2127 U5.14@4738,2187
NetP2_2: P2.2 U5.24 | length 1014.5
  Top Layer w8: P2.2@3955,1980 3918,2017 3906.79,2017 3876,2047.79 3876,2295.77 4039.23,2459 4060.77,2459 4070.77,2449 4298.63,2449 4310.63,2437 4388,2437 U5.24@4438,2487
NetP2_3: P2.3 U5.36 | length 390.9
  Top Layer w8: P2.3@3955,1880 3955,1912 4067,2024 4175,2024 4191,2040 4191,2045.77 4232.23,2087 U5.36@4238,2087
NetP2_4: P2.4 U5.33 | length 492.2
  Top Layer w8: v1(4069,2134) 4122,2187 U5.33@4138,2187
  Bottom Layer w8: P2.4@3955,1780 4033,1858 4033,2098 v1(4069,2134)
NetP3_2: P3.2 U5.13 | length 1761.5
  Top Layer w8: P3.2@3785,1890 3867,1808 3867,1698 3918,1647 4783,1647 4881,1745 4881,2144 U5.13@4838,2187
NetP5_1: U5.44
NetP5_2: U5.3
NetP5_3: U5.43
NetP5_4: U5.4
NetP5_5: U5.42
NetP5_6: U5.5
NetP5_7: U5.41
NetP5_8: U5.6
NetP5_9: U5.40
NetP5_10: U5.7
NetP5_11: U5.39
NetP5_12: U5.8
NetP5_13: U5.38
NetP5_14: U5.9
NetP5_15: U5.37
NetP5_16: U5.10
NetQ1_1: Q1.1 R67.2 | length 67.1
  Bottom Layer w8: R67.2@4570,459.53 4572.4,461.93 Q1.1@4572.4,525.63
NetQ1_3: Q1.3 R57.2 | length 88.2
  Bottom Layer w8: Q1.3@4535,604.37 4540,609.37 R57.2@4540,690.47
NetR16_1: R16.1 U1.71 U15.5 | length 1514.6
  Top Layer w8: R16.1@1709.53,2126 1812,2126 U15.5@1814,2124 1848,2090 v1(2299,2090) ; v1(2299,2220) v1(2411,2332) ; U1.71@2773.54,2499.41 2773.54,2441.46 2803,2412 v1(2805,2412)
  Bottom Layer w8: v1(2299,2090) v1(2299,2220) ; v1(2411,2332) 2411,2405 2478.69,2472.69 2742.31,2472.69 2803,2412 v1(2805,2412)
NetR17_1: R17.1 U1.72 U15.6 | length 1542.1
  Top Layer w8: R17.1@1707.53,2026 1812,2026 U15.6@1814,2024 ; v1(2166,2149) v1(2383,2366) ; U1.72@2793.23,2499.41 2796.01,2496.63 2796.01,2440.3 2796.13,2440.18 2832.82,2440.18 v1(2859,2414)
  Bottom Layer w8: U15.6@1814,2024 1939,2024 2070,2155 2160,2155 v1(2166,2149) ; v1(2383,2366) 2383,2414 2456.69,2487.69 2785.31,2487.69 v1(2859,2414)
NetR19_2: R19.2 U16.27 | length 666.5
  Top Layer w8: R19.2@2289.53,1278 2448,1278 2493,1233 2607.77,1233 2674.71,1299.94 U16.27@2909.64,1299.94
NetR25_1: R25.1 R32.2 U17.10 | length 519.8
  Top Layer w8: R25.1@1562.47,5452 1564,5453.53 1564,5495.76 ; R32.2@1564,5538 1564,5495.76 ; U17.10@1920.82,5680 1841,5680 1656.76,5495.76 1564,5495.76
NetR25_2: R25.2 U17.9 | length 441.3
  Top Layer w8: R25.2@1621.53,5452 1756,5452 1946.41,5642.41 U17.9@1946.41,5680
NetR26_2: R26.2 R31.1 U17.11 | length 695.8
  Top Layer w8: R31.1@1376.47,5488 1376.47,5502.94 R26.2@1439.53,5566 1502,5503.53 1502,5452 1545,5409 1884.07,5409 U17.11@1920.82,5445.75
NetR28_2: R28.2 U16.21 | length 665.1
  Top Layer w8: U16.21@2781.68,1191.67 2781.68,1142.32 2820.46,1103.54 3327.01,1103.54 R28.2@3365.47,1142
NetR29_2: R29.2 U16.20 | length 687.8
  Top Layer w10: U16.20@2762,1191.67 2762,1120 2794.46,1087.54 3364.01,1087.54 R29.2@3364.47,1088
NetR31_2: R31.2 U17.12 | length 635.7
  Top Layer w8: R31.2@1435.53,5488 1435.53,5453.47 1505,5384 1946,5384 1946.41,5384.41 U17.12@1946.41,5445.75
NetR40_1: R40.1 U16.24 | length 64.5
  Top Layer w8: U16.24@2840.74,1191.67 v1(2873.67,1191.67)
  Bottom Layer w8: v1(2873.67,1191.67) 2890,1208 2890,1204.47 R40.1@2893.47,1201
NetR47_1: R47.1 R48.2 REG_1V8.1 | length 175
  Top Layer w10: REG_1V8.1@841,964 916,964 ; R47.1@946,994 916,964 ; R48.2@946.47,919 946.47,933.53 916,964
NetR49_1: R49.1 R50.2 REG_5V.1 | length 179.7
  Top Layer w8: REG_5V.1@839,2783 931.47,2783 R50.2@946.47,2768 R49.1@946.47,2834
NetR51_1: R51.1 R52.2 REG_3V3.1 | length 190
  Top Layer w10: REG_3V3.1@843,2187 848,2182 R52.2@958.47,2182 959.47,2183 R51.1@959.47,2254
NetR53_1: R53.1 R54.2 REG_3V.1 | length 190.6
  Top Layer w8: REG_3V.1@842,1590 904.47,1590 ; R54.2@954.47,1572 922.47,1572 904.47,1590 ; R53.1@954.47,1640 904.47,1590
NetR55_1: R55.1 U20.27 | length 174.1
  Bottom Layer w10: R55.1@5940.53,4373 6109,4373 U20.27@6113,4377
NetR56_1: R56.1 U20.2 | length 207.1
  Bottom Layer w10: R56.1@5934.06,1945 6045,1945 U20.2@6113,1877
NetR57_1: R57.1 U3.5 | length 410.9
  Bottom Layer w8: R57.1@4540,749.53 4886.47,749.53 U3.5@4932,704
NetR58_2: R58.2 REG_1V8.3 | length 213.9
  Bottom Layer w30: REG_1V8.3@841,1164 983.2,1306.2 R58.2@983.2,1319
NetR59_1: R59.1 U16.7 | length 313
  Top Layer w8: R59.1@2280,1450 2371.01,1358.99 U16.7@2555.31,1358.99
NetR60_1: R60.1 REG_5V.3 | length 193.1
  Bottom Layer w30: REG_5V.3@839,2983 839,3052.8 R60.1@926.2,3140
NetR61_1: R61.1 REG_3V3.3 | length 184.8
  Bottom Layer w30: REG_3V3.3@843,2387 843,2442.8 R61.1@934.2,2534
NetR62_1: R62.1 REG_3V.3 | length 196.5
  Bottom Layer w30: REG_3V.3@842,1790 842,1827.8 R62.1@954.2,1940
NetR63_1: R63.1 R64.2 U17.13 | length 1372.7
  Top Layer w8: U17.13@1972,5445.75 1972,5392 v1(1989,5375) ; v1(2179,5377) v1(2278,5377) ; v1(2406,5505) 2497,5596 2566.21,5596 2586,5615.79 2586,5685 2696.47,5795.47 R64.2@2990,5795.47 2990,5724.53 R63.1@2985,5719.53
  Bottom Layer w8: v1(1989,5375) 1989,5377 v1(2179,5377) ; v1(2278,5377) v1(2406,5505)
NetR65_1: R65.1 SW_RESET.1 | length 312.1
  Bottom Layer w8: R65.1@5479.53,593 5547,593 SW_RESET.1@5720,420
NetU1_171: U1.171 U8.46 | length 820.4
  Top Layer w8: U1.171@3147.56,3698.23 3150.34,3695.45 3150.34,3637.59 3194.93,3593 v1(3198,3593) ; v1(3626,3937) 3629.94,3940.94 3629.94,4017.22 U8.46@3627.17,4020
  Bottom Layer w8: v1(3198,3593) 3200,3591 3221.79,3591 3225.79,3595 3239.79,3595 3251.79,3607 3355,3607 3626,3878 v1(3626,3937)
NetU1_172: U1.172 U8.44 | length 758.5
  Top Layer w8: v1(3127.87,3616.13) U1.172@3127.87,3698.23 ; U8.44@3587.8,4020 3589,4018.8 v1(3589,3943)
  Bottom Layer w8: v1(3127.87,3616.13) 3130.75,3619 3208.77,3619 3211.64,3616.13 3239.7,3616.13 3245.57,3622 3268,3622 v1(3589,3943)
NRD: U1.170 U4.1 U4.24 U8.47 U18.1 U18.24 | length 5271.6
  Top Layer w8: v1(2587,4235) 2587,4302.59 U4.24@2594.41,4310 ; v1(2679,4211) 2942,4211 2952,4201 v1(3159,4201) 3159,4141 3147,4129 v1(3147,4075) ; U4.1@3047.17,4310 3079.17,4278 v1(3113,4278) ; v1(3147,3779) 3167.24,3758.76 U1.170@3167.24,3698.23 3170.02,3695.45 3170.02,3639.12 3170.14,3639 3188.77,3639 3231,3596.77 v1(3231,3565) ; U8.47@3646.85,4020 3646.85,3957.15 3658,3946 v1(3658,3801) 3664,3795 v1(3765,3795) ; v1(4465,3981) v1(4548,3981) ; U18.24@5201.58,4916.34 5201.58,4983 ; v1(5223,4983) 5201.58,4983 ; 5654,4955 5654,5053 5615,5092 5256,5092 5201.58,5037.58 5201.58,4983
  Bottom Layer w8: v1(2587,4235) 2611,4211 v1(2679,4211) ; v1(3113,4278) 3113,4226 3138,4201 v1(3159,4201) ; v1(3147,3779) v1(3147,4075) ; v1(3231,3565) 3258,3592 3451,3592 3659,3800 v1(3658,3801) ; v1(3765,3795) 4279,3795 v1(4465,3981) ; v1(4548,3981) 4648,4081 4648,4408 v1(5223,4983)
NRD_NOE_3V3_BUF: U6.41 U7.24 U8.2 | length 3865.4
  Top Layer w8: v1(3547,6024) 3547,6071.23 3545,6073.23 3545,6105.77 3565.23,6126 3810,6126 3877.53,6058.47 U6.41@3877.53,5944.08 ; U8.2@3646.85,4311.34 3646.85,4366.38 3638.78,4374.45 3638.78,4395.99 3646.85,4404.06 3646.85,4486.85 v1(3649,4489) ; v1@3878,6017 v1(3879,6018) ; v1(4448,5697) 4448,5590 4637,5401 4695,5401 4709,5415 4709,5493 U7.24@4762,5546 ; v1(4475,5766) v1(4475,5998)
  Bottom Layer w8: v1(3547,6024) 3547,4719 3649,4617 v1(3649,4489) ; v1(3879,6018) 4030.23,6018 4047.23,6035 4438,6035 v1(4475,5998) ; v1(4448,5697) 4448,5739 v1(4475,5766)
NTRST: P6.6 U1.110 U5.17 | length 2996.3
  Top Layer w8: U5.17@4838,2387 5040,2387 v1(5113,2314)
  Top Layer w10: U1.110@3520.59,2695.28 3504.78,2695.28 U1.110@3503,2693.5 ; v1(3995,2683) v1@3984.5,2693.5 ; v1(4183,2683) 4394,2683 v1(4478,2599) ; U1.110@3503,2693.5 3520.59,2693.5 v1@3984.5,2693.5 ; U1.110@3503,2693.5 v1@3984.5,2693.5
  Bottom Layer w8: v1(5113,2314) 5404,2023 5404,1894 P6.6@5319,1809
  Bottom Layer w10: v1(3995,2683) v1(4183,2683) ; v1(4478,2599) 4743,2599 4838,2504 U5.17@4838,2387
NWAIT: P6.5 U1.25 U5.27 | length 4296.4
  Top Layer w8: v1(4289,2184) 4284,2189 4284,2425 4292,2433 ; v1(4291,2111) 4456,1946 v1(4493,1946) ; v1(4951,1941) 5087,1941 P6.5@5219,1809
  Top Layer w10: v1(2251,3252) 2251,3141.37 2262.25,3130.13 2319.99,3130.13 U1.25@2321.77,3128.35 ; v1(2392,3313) 2392,3319 v1(2431,3358) ; v1(2476,3295) 2781,3295 v1(3067,3009) ; v1(3289,3009) 3412,3009 v1(3446,2975) ; v1(4050,2433) 4292,2433 U5.27@4338,2387
  Bottom Layer w8: v1(4289,2184) 4289,2113 v1(4291,2111) ; v1(4493,1946) 4498,1941 4566.79,1941 4583,1957.21 4583,1972.77 4598.23,1988 4686.09,1988 4723.09,1951 4749.21,1951 4759.21,1941 v1(4951,1941)
  Bottom Layer w10: v1(2251,3252) 2306,3307 2386,3307 v1(2392,3313) ; v1(2431,3358) 2431,3340 v1(2476,3295) ; v1(3067,3009) v1(3289,3009) ; v1(3446,2975) 3700,2975 3968,2707 3968,2671.82 3983.82,2656 4019,2656 4050,2625 v1(4050,2433)
NWE_3V3_BUF: P6.3 U5.26 U6.17 U7.31 U8.3 | length 6239.9
  Top Layer w8: v1(3623,4691) 3629.94,4684.06 3629.94,4506.71 3623,4499.77 3623,4478.23 3629.94,4471.29 3629.94,4408.37 3623.78,4402.2 3623.78,4368.24 3631.85,4360.17 3631.85,4351.74 3629.94,4349.84 3629.94,4314.12 U8.3@3627.17,4311.34 3627.17,4257.83 3638,4247 3686,4247 v1(3736,4297) ; v1(3736,3089) U5.26@4338,2487 4396,2545 v1(4424,2545) ; U6.17@4286.98,5454 4286.98,5365.02 v1(4385,5267) 4389,5263 v1(4877,5263) ; v1(4596,2546) 4596,2465 4629,2432 5114,2432 5128,2418 5128,2406.23 5143.23,2391 5155,2391 5259.53,2286.47 5259.53,1974.92 5253.08,1968.47 5231.06,1968.47 5219,1956.41 P6.3@5219,1909
  Bottom Layer w8: v1(3623,4691) 3683,4751 3862.77,4751 4101,4989.23 4101,4990 4378,5267 v1(4385,5267) ; v1(3736,3089) v1(3736,4297) ; v1(4424,2545) 4595,2545 v1(4596,2546) ; v1(4877,5263) 5005,5391 5005,5489 U7.31@5062,5546
PCK0: P6.7 U1.122 U5.11 U5.28 | length 2380.4
  Top Layer w8: v1(4982,1900) 5015,1867 5061,1867 P6.7@5219,1709
  Top Layer w10: U1.122@3520.59,2931.5 3793.5,2931.5 U5.28@4238,2487 ; v1(4310,2328) 4763,2328 4801,2290 4801,2124 U5.11@4838,2087
  Bottom Layer w8: U5.11@4838,2087 4841.77,2087 4982,1946.77 v1(4982,1900)
  Bottom Layer w10: U5.28@4238,2487 4292,2433 4292,2346 v1(4310,2328)
PCK1: P6.9 U1.70 U5.29 | length 3151.2
  Top Layer w8: U5.29@4138,2387 4189,2336 v1(4189,2231) ; v1(4217,2035) 4272,2035 4384,1923 4452.91,1923 4466.91,1909 v1(4482.47,1909) ; v1(4943,1658) 5037.23,1658 5053.23,1642 5074.77,1642 5090.77,1658 5170,1658 P6.9@5219,1609
  Top Layer w10: U1.70@2753.86,2499.41 2752.08,2497.63 2752.08,2414.92 v1(2757,2410)
  Bottom Layer w8: v1(4189,2231) 4189,2063 v1(4217,2035) ; v1(4482.47,1909) 4482.47,1902.53 4502,1883 4502,1872.09 4523.09,1851 4724.91,1851 4774,1801.91 4774,1793 4909,1658 v1(4943,1658)
  Bottom Layer w10: v1(2757,2410) 2782,2385 2897.84,2385 2899.84,2383 3160.37,2383 3187,2409.63 3187,2425.18 3202.82,2441 3225.18,2441 3241,2425.18 3241,2411.63 3279.63,2373 4124,2373 U5.29@4138,2387
PFI: R3.1 R4.2 U3.4 | length 175.7
  Bottom Layer w8: R4.2@5126,613.53 5126,668.47 R3.1@5128,670.47 5161.53,704 U3.4@5232,704
RAS: P6.8 R55.2 U5.18 | length 3581
  Top Layer w8: v1(4923,3268) 4923,2672 U5.18@4738,2487 v1(5084,2487) ; v1(5154,2417) 5276,2295 5276,1752 P6.8@5319,1709
  Bottom Layer w8: v1(4923,3268) 4923,3414.53 R55.2@5881.47,4373 ; v1(5084,2487) v1(5154,2417)
RD0: U1.83 U17.17 | length 3398.6
  Top Layer w10: U17.17@2074.36,5445.75 2074.36,5362.36 2067,5355 2067,5245 v1(2117,5195) ; v1(2516.62,3626.62) 2556.63,3586.61 2556.63,3570.74 2604,3523.37 2604,3499.82 2619.82,3484 2659.25,3484 v1(2715.62,3427.62) ; U1.83@3009.76,2499.41 3009.76,2717.84 3035.74,2743.82 v1(3035.74,2745)
  Bottom Layer w10: v1(2117,5195) 2100,5178 2100,4447 2516.62,4030.38 v1(2516.62,3626.62) ; v1(2715.62,3427.62) 2716.46,3426.79 2716.46,3390.05 3035.74,3070.78 v1(3035.74,2745)
RESET: P6.4 R66.1 U1.115 U3.7 U5.16 U5.35 U16.29 U17.2 | length 19473.3
  Top Layer w8: U17.2@2125.54,5680 2125.54,5733.54 2144,5752 2262,5752 2400,5614 2530,5614 2571,5655 2571,5726 2601,5756 v1(2601,5761) ; v1(2609,5885) 3085,6361 5583,6361 6462,5482 6462,1011 5787,336 4948,336 4856,428 U3.7@4932,504 ; U16.29@2909.64,1339.31 2975.54,1339.31 2978.23,1342 3072.77,1342 3083.77,1331 3718,1331 v1(3793,1406) ; U1.115@3520.59,2793.7 v1(3650.3,2793.7) ; v1(3895,1542) 3955,1602 v1(3980,1602) ; v1(4017,2400) 4048,2369 4048,2287 3891,2130 3891,2054 3906,2039 4065,2039 ; v1(4065,1687) v1(4065,1958) ; v1(4065,2056) 4065,2039 ; v1(4571,2105) 4550,2126 4540.77,2126 4536.77,2130 4515.23,2130 4511.23,2126 4345.46,2126 4337.46,2134 4304.77,2134 4301.77,2137 4280.23,2137 4277.23,2134 4185,2134 U5.35@4138,2087 4090,2039 4065,2039 ; v1(4571,2170) 4621,2170 U5.16@4738,2287 4785,2240 v1(4785,1705) ; v1(4704,406) 4802,504 U3.7@4932,504 ; v1(4785,1596) 4785,1519 4858,1446 4858,578 U3.7@4932,504 ; 4858,773 5278,773 5478,973 5478,1750 P6.4@5319,1909
  Bottom Layer w8: v1(2601,5761) 2601,5877 v1(2609,5885) ; v1(3650.3,2793.7) 4017,2427 v1(4017,2400) ; v1(3793,1406) 3793,1440 v1(3895,1542) ; v1(3980,1602) v1(4065,1687) ; v1(4065,1958) v1(4065,2056) ; v1(4571,2105) v1(4571,2170) ; R66.1@4650,400.47 4655.53,406 v1(4704,406) ; v1(4785,1596) v1(4785,1705)
ROW_ADDR_EN: P6.14 R45.1 U5.21 U19.25 U19.48 | length 2860.3
  Top Layer w8: U19.25@4478.66,3272.17 4401.17,3272.17 4197,3068 4197,2816 4226.23,2816 4229.14,2813.1 4472.35,2813.1 U19.48@4478.66,2819.41 4593,2705.07 4593,2579.77 4570,2556.77 4570,2535.23 4575,2530.23 4575,2450 U5.21@4638,2387
  Bottom Layer w8: U5.21@4638,2387 R45.1@4638,2288.53 4681.06,2245.47 4972.16,2245.47 5026,2191.63 5026,1844.69 5202.21,1668.47 5216.84,1668.47 5278.47,1606.84 5278.47,1492.21 5319,1451.69 P6.14@5319,1409
TCK: P1.9 R9.1 U1.108 | length 2291
  Top Layer w8: 3861.19,1482.33 4072.99,1270.53 4526.79,1270.53 4567.31,1230 P1.9@4610,1230
  Top Layer w10: U1.108@3520.59,2655.91 3586.89,2655.91 3624.82,2617.97 3624.82,1718.7 3861.19,1482.33
  Bottom Layer w10: P1.9@4610,1230 4614,1234 R9.1@4614,1312.47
